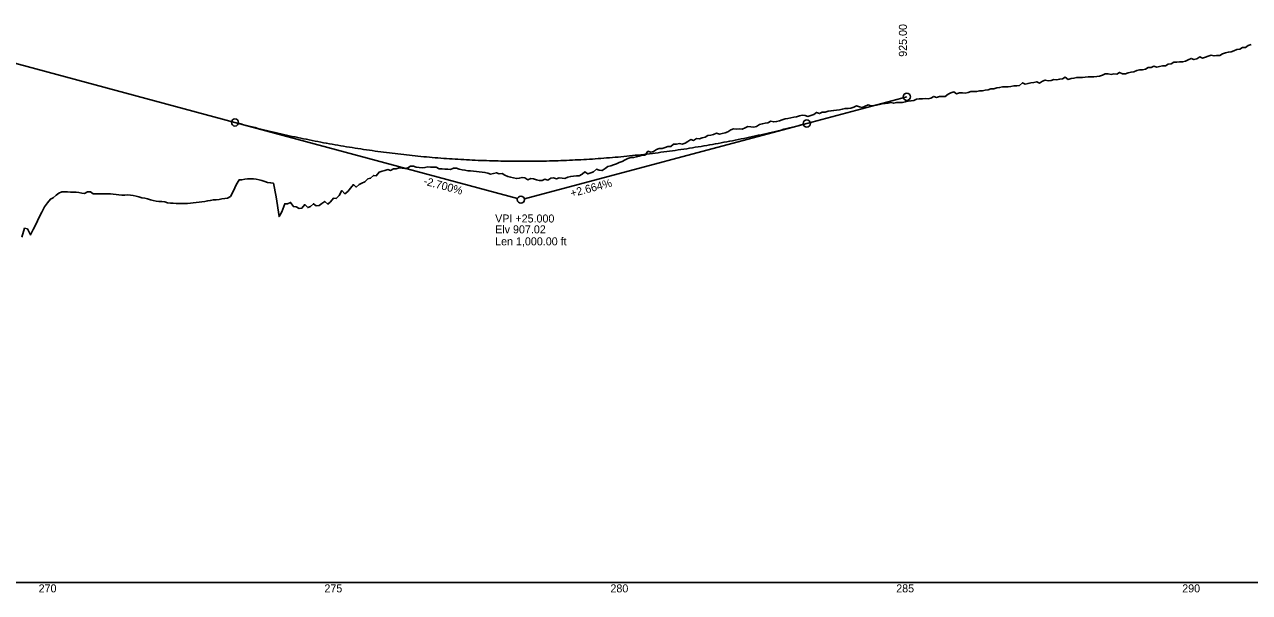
# Model space of a CAD drawing. Extents: x 5180909 to 5237144, y 3695282 to 3720102.
# Drawn here: x 5230717 to 5232860, y 3697765 to 3698758 of the extents above; entities that cross this region are included whole.
import ezdxf

# ---------------------------------------------------------------- set-up
doc = ezdxf.new("R2010")
doc.units = 0
for name, color, linetype in [('dsnEntranceGranular', 7, 'Continuous'), ('dsnShoulderGran', 7, 'Continuous'), ('dsnShoulderPaved', 7, 'Continuous'), ('dsnStgShadingPropGrdLim', 7, 'Continuous'), ('EdgeShoulder', 7, 'Continuous'), ('Entrance', 7, 'Continuous')]:
    doc.layers.add(name, color=color, linetype=linetype)

msp = doc.modelspace()

# ---------------------------------------------------------------- linework, layer by layer
at = {"layer": 'dsnEntranceGranular'}
msp.add_line((5221643.6, 3697782), (5237143.6, 3697782), dxfattribs=at)
at = {"layer": 'dsnShoulderPaved'}
for points in [[(5232642.7, 3698672.4), (5232647.7, 3698674.2), (5232652.7, 3698675.2), (5232657.7, 3698675.8), (5232662.7, 3698677.9), (5232667.7, 3698678.9), (5232672.7, 3698679), (5232677.7, 3698680.2), (5232682.7, 3698683.2), (5232687.7, 3698683.4), (5232692.7, 3698685.6), (5232697.7, 3698683.6), (5232702.7, 3698685.1), (5232707.7, 3698685.9), (5232712.7, 3698686.4), (5232717.7, 3698688.8), (5232722.7, 3698689.4), (5232727.7, 3698692.5), (5232732.7, 3698692.5), (5232737.7, 3698692.9), (5232742.7, 3698693), (5232747.7, 3698694.6), (5232752.7, 3698696.4), (5232757.7, 3698699.2), (5232762.7, 3698697.2), (5232767.7, 3698698.2), (5232772.7, 3698701.8), (5232777.7, 3698699.4), (5232782.7, 3698701.5), (5232787.7, 3698702.8), (5232792.7, 3698704.7), (5232797.7, 3698703.4), (5232802.7, 3698704.3), (5232807.7, 3698704.4), (5232812.7, 3698707.4), (5232817.7, 3698709.2), (5232822.7, 3698709.8), (5232827.7, 3698710.9), (5232832.7, 3698712.3), (5232837.7, 3698715), (5232842.7, 3698715.2), (5232847.7, 3698718.3), (5232852.7, 3698718.3), (5232857.7, 3698721.6), (5232862.7, 3698723.6)], [(5232142.7, 3698609), (5232147.7, 3698610.3), (5232152.7, 3698611.8), (5232157.7, 3698611.8), (5232162.7, 3698612.1), (5232167.7, 3698613.9), (5232172.7, 3698616), (5232177.7, 3698614.5), (5232182.7, 3698613.5), (5232187.7, 3698615.6), (5232192.7, 3698618.1), (5232197.7, 3698616.2), (5232202.7, 3698616.5), (5232207.7, 3698617.6), (5232212.7, 3698618.6), (5232217.7, 3698619.5), (5232222.7, 3698620.3), (5232227.7, 3698621.1), (5232232.7, 3698621.9), (5232237.7, 3698620.8), (5232242.7, 3698622.3), (5232247.7, 3698622.3), (5232252.7, 3698622.1), (5232257.7, 3698623), (5232262.7, 3698624.3), (5232267.7, 3698624.9), (5232272.7, 3698625.8), (5232277.7, 3698627.6), (5232282.7, 3698628.7), (5232287.7, 3698628.6), (5232292.7, 3698629.1), (5232297.7, 3698628.5), (5232302.7, 3698629.4), (5232307.7, 3698632.6), (5232312.7, 3698630.9), (5232317.7, 3698632.7), (5232322.7, 3698632.7), (5232327.7, 3698632.7), (5232332.7, 3698636.5), (5232337.7, 3698638.8), (5232342.7, 3698640.5), (5232347.7, 3698637.4), (5232352.7, 3698638.7), (5232357.7, 3698638.8), (5232362.7, 3698638.6), (5232367.7, 3698639.8), (5232372.7, 3698641.2), (5232377.7, 3698641), (5232382.7, 3698641.4), (5232387.7, 3698642.3), (5232392.7, 3698642.7), (5232397.7, 3698643.8), (5232402.7, 3698643.9), (5232407.7, 3698645.9), (5232412.7, 3698645.9), (5232417.7, 3698647.4), (5232422.7, 3698648.1), (5232427.7, 3698649.4), (5232432.7, 3698649.3), (5232437.7, 3698649.7), (5232442.7, 3698650.3), (5232447.7, 3698651.1), (5232452.7, 3698651.1), (5232457.7, 3698652), (5232462.7, 3698656.5), (5232467.7, 3698654.3), (5232472.7, 3698655.5), (5232477.7, 3698656.4), (5232482.7, 3698657.2), (5232487.7, 3698658.4), (5232492.7, 3698656), (5232497.7, 3698659.1), (5232502.7, 3698661.2), (5232507.7, 3698660.2), (5232512.7, 3698660.5), (5232517.7, 3698662.2), (5232522.7, 3698661.8), (5232527.7, 3698662.6), (5232532.7, 3698663.7), (5232537.7, 3698666.1), (5232542.7, 3698662.5), (5232547.7, 3698663.8), (5232552.7, 3698664.5), (5232557.7, 3698665.9), (5232562.7, 3698665.5), (5232567.7, 3698665.8), (5232572.7, 3698666.3), (5232577.7, 3698667), (5232582.7, 3698667), (5232587.7, 3698667), (5232592.7, 3698667.4), (5232597.7, 3698667.9), (5232602.7, 3698670), (5232607.7, 3698672.1), (5232612.7, 3698672), (5232617.7, 3698671.2), (5232622.7, 3698672), (5232627.7, 3698671.6), (5232632.7, 3698674.7), (5232637.7, 3698672), (5232642.7, 3698672.4)], [(5231642.7, 3698490.2), (5231647.7, 3698488.3), (5231652.7, 3698490.4), (5231657.7, 3698489.6), (5231662.7, 3698488.8), (5231667.7, 3698491.2), (5231672.7, 3698492.7), (5231677.7, 3698493.1), (5231682.7, 3698493.7), (5231687.7, 3698494), (5231692.7, 3698496.5), (5231697.7, 3698500.5), (5231702.7, 3698497), (5231707.7, 3698498.8), (5231712.7, 3698501), (5231717.7, 3698505.1), (5231722.7, 3698503.7), (5231727.7, 3698502.8), (5231732.7, 3698506.4), (5231737.7, 3698509.9), (5231742.7, 3698511.5), (5231747.7, 3698512.9), (5231752.7, 3698514.7), (5231757.7, 3698517.3), (5231762.7, 3698519), (5231767.7, 3698521.9), (5231772.7, 3698523.9), (5231777.7, 3698525.8), (5231782.7, 3698525.7), (5231787.7, 3698527), (5231792.7, 3698528), (5231797.7, 3698529.8), (5231802.7, 3698530.1), (5231807.7, 3698536.7), (5231812.7, 3698535.2), (5231817.7, 3698536.5), (5231822.7, 3698539.6), (5231827.7, 3698541.5), (5231832.7, 3698541.8), (5231837.7, 3698543.2), (5231842.7, 3698544.9), (5231847.7, 3698544.8), (5231852.7, 3698549.1), (5231857.7, 3698549.3), (5231862.7, 3698550.2), (5231867.7, 3698549.1), (5231872.7, 3698550.8), (5231877.7, 3698553.7), (5231882.7, 3698557), (5231887.7, 3698555.8), (5231892.7, 3698559.3), (5231897.7, 3698558.6), (5231902.7, 3698560), (5231907.7, 3698561.5), (5231912.7, 3698564), (5231917.7, 3698564.6), (5231922.7, 3698566), (5231927.7, 3698568.3), (5231932.7, 3698566.8), (5231937.7, 3698567.8), (5231942.7, 3698568.8), (5231947.7, 3698570.9), (5231952.7, 3698574.1), (5231957.7, 3698575.8), (5231962.7, 3698575.4), (5231967.7, 3698575.7), (5231972.7, 3698575.5), (5231977.7, 3698577.8), (5231982.7, 3698580), (5231987.7, 3698579.5), (5231992.7, 3698579), (5231997.7, 3698580.3), (5232002.7, 3698583.5), (5232007.7, 3698584.5), (5232012.7, 3698585.8), (5232017.7, 3698586.5), (5232022.7, 3698589.5), (5232027.7, 3698588.1), (5232032.7, 3698588.5), (5232037.7, 3698590), (5232042.7, 3698591.7), (5232047.7, 3698593.4), (5232052.7, 3698594.3), (5232057.7, 3698595.4), (5232062.7, 3698596.3), (5232067.7, 3698597.2), (5232072.7, 3698598.8), (5232077.7, 3698600.1), (5232082.7, 3698599.4), (5232087.7, 3698597.8), (5232092.7, 3698599.5), (5232097.7, 3698601.2), (5232102.7, 3698604.7), (5232107.7, 3698602.6), (5232112.7, 3698605), (5232117.7, 3698605.2), (5232122.7, 3698606.6), (5232127.7, 3698607.2), (5232132.7, 3698608.3), (5232137.7, 3698608.6), (5232142.7, 3698609)], [(5231142.7, 3698481.8), (5231147.7, 3698481.6), (5231152.7, 3698480.7), (5231157.7, 3698456.8), (5231162.7, 3698422.4), (5231167.7, 3698431), (5231172.7, 3698444.9), (5231177.7, 3698444.6), (5231182.7, 3698447.3), (5231187.7, 3698440), (5231192.7, 3698439.5), (5231197.7, 3698436.6), (5231202.7, 3698437.2), (5231207.7, 3698443.3), (5231212.7, 3698438.1), (5231217.7, 3698440.1), (5231222.7, 3698444.8), (5231227.7, 3698441.4), (5231232.7, 3698441.8), (5231237.7, 3698445.6), (5231242.7, 3698449.1), (5231247.7, 3698444.4), (5231252.7, 3698448.5), (5231257.7, 3698454.6), (5231262.7, 3698454.1), (5231267.7, 3698459.4), (5231272.7, 3698467.8), (5231277.7, 3698462.5), (5231282.7, 3698466.6), (5231287.7, 3698471.9), (5231292.7, 3698478.5), (5231297.7, 3698474.1), (5231302.7, 3698478.5), (5231307.7, 3698480.7), (5231312.7, 3698483.1), (5231317.7, 3698488.3), (5231322.7, 3698489.5), (5231327.7, 3698494.4), (5231332.7, 3698493.8), (5231337.7, 3698500.1), (5231342.7, 3698501.6), (5231347.7, 3698503), (5231352.7, 3698504.6), (5231357.7, 3698503.1), (5231362.7, 3698505.7), (5231367.7, 3698506), (5231372.7, 3698507.5), (5231377.7, 3698507.3), (5231382.7, 3698506.5), (5231387.7, 3698507.6), (5231392.7, 3698510.4), (5231397.7, 3698510.6), (5231402.7, 3698508.8), (5231407.7, 3698508.4), (5231412.7, 3698507.8), (5231417.7, 3698508.2), (5231422.7, 3698509.2), (5231427.7, 3698508.9), (5231432.7, 3698508.9), (5231437.7, 3698508.7), (5231442.7, 3698506), (5231447.7, 3698505.8), (5231452.7, 3698505.6), (5231457.7, 3698505.5), (5231462.7, 3698504.9), (5231467.7, 3698507), (5231472.7, 3698507.2), (5231477.7, 3698505.2), (5231482.7, 3698504.4), (5231487.7, 3698503.7), (5231492.7, 3698502.6), (5231497.7, 3698502.3), (5231502.7, 3698502), (5231507.7, 3698501.5), (5231512.7, 3698500.7), (5231517.7, 3698500), (5231522.7, 3698499.6), (5231527.7, 3698498.2), (5231532.7, 3698496.8), (5231537.7, 3698498.1), (5231542.7, 3698499.1), (5231547.7, 3698497.5), (5231552.7, 3698497.8), (5231557.7, 3698495.1), (5231562.7, 3698492.4), (5231567.7, 3698491.4), (5231572.7, 3698490.2), (5231577.7, 3698488.9), (5231582.7, 3698489.6), (5231587.7, 3698491.1), (5231592.7, 3698490), (5231597.7, 3698486.8), (5231602.7, 3698488.8), (5231607.7, 3698488.5), (5231612.7, 3698486.8), (5231617.7, 3698485.3), (5231622.7, 3698485.6), (5231627.7, 3698487.9), (5231632.7, 3698486.4), (5231637.7, 3698489.8), (5231642.7, 3698490.2)], [(5230712.7, 3698386.6), (5230717.7, 3698401.9), (5230722.7, 3698400.9), (5230727.7, 3698390.5), (5230732.7, 3698399.6), (5230737.7, 3698410), (5230742.7, 3698420.5), (5230747.7, 3698430.3), (5230752.7, 3698439.4), (5230757.7, 3698446.2), (5230762.7, 3698452.7), (5230767.7, 3698455.2), (5230772.7, 3698460.1), (5230777.7, 3698463.5), (5230782.7, 3698466), (5230787.7, 3698465.9), (5230792.7, 3698465.6), (5230797.7, 3698465.4), (5230802.7, 3698465.2), (5230807.7, 3698465.1), (5230812.7, 3698464.3), (5230817.7, 3698463.6), (5230822.7, 3698462.9), (5230827.7, 3698465.9), (5230832.7, 3698465.8), (5230837.7, 3698462.3), (5230842.7, 3698462.1), (5230847.7, 3698462.1), (5230852.7, 3698462.1), (5230857.7, 3698462), (5230862.7, 3698462), (5230867.7, 3698462.1), (5230872.7, 3698461.5), (5230877.7, 3698461), (5230882.7, 3698460.3), (5230887.7, 3698459.7), (5230892.7, 3698459.9), (5230897.7, 3698460.2), (5230902.7, 3698460.1), (5230907.7, 3698459.3), (5230912.7, 3698458.4), (5230917.7, 3698457), (5230922.7, 3698455.5), (5230927.7, 3698454.4), (5230932.7, 3698453.2), (5230937.7, 3698451.8), (5230942.7, 3698450.5), (5230947.7, 3698449.6), (5230952.7, 3698448.7), (5230957.7, 3698448.6), (5230962.7, 3698448.1), (5230967.7, 3698446.5), (5230972.7, 3698446.1), (5230977.7, 3698446), (5230982.7, 3698445.6), (5230987.7, 3698445.3), (5230992.7, 3698445.1), (5230997.7, 3698445.3), (5231002.7, 3698445.6), (5231007.7, 3698445.9), (5231012.7, 3698446.5), (5231017.7, 3698447.3), (5231022.7, 3698447.9), (5231027.7, 3698448.5), (5231032.7, 3698449), (5231037.7, 3698449.7), (5231042.7, 3698450.7), (5231047.7, 3698451.5), (5231052.7, 3698452), (5231057.7, 3698452.6), (5231062.7, 3698453.6), (5231067.7, 3698454.1), (5231072.7, 3698454.6), (5231077.7, 3698457.6), (5231082.7, 3698467.5), (5231087.7, 3698477.8), (5231092.7, 3698486.7), (5231097.7, 3698487), (5231102.7, 3698487.7), (5231107.7, 3698488.4), (5231112.7, 3698488.5), (5231117.7, 3698488.3), (5231122.7, 3698487.7), (5231127.7, 3698486.6), (5231132.7, 3698485.5), (5231137.7, 3698483.7), (5231142.7, 3698481.8)]]:
    msp.add_lwpolyline(points, dxfattribs=at)
at = {"layer": 'dsnStgShadingPropGrdLim'}
for p, q in [((5230685.6, 3698695.1), (5231085.6, 3698587.1)), ((5232085.6, 3698585.3), (5232260.6, 3698632))]:
    msp.add_line(p, q, dxfattribs=at)
msp.add_spline([(5231085.6, 3698587.1), (5231105.6, 3698581.8), (5231125.6, 3698576.8), (5231145.6, 3698571.9), (5231165.6, 3698567.3), (5231185.6, 3698562.8), (5231205.6, 3698558.6), (5231225.6, 3698554.6), (5231245.6, 3698550.8), (5231265.6, 3698547.2), (5231285.6, 3698543.9), (5231305.6, 3698540.7), (5231325.6, 3698537.8), (5231345.6, 3698535.1), (5231365.6, 3698532.6), (5231385.6, 3698530.3), (5231405.6, 3698528.2), (5231425.6, 3698526.3), (5231445.6, 3698524.7), (5231465.6, 3698523.3), (5231485.6, 3698522.1), (5231505.6, 3698521), (5231525.6, 3698520.3), (5231545.6, 3698519.7), (5231565.6, 3698519.3), (5231585.6, 3698519.2), (5231605.6, 3698519.3), (5231625.6, 3698519.5), (5231645.6, 3698520), (5231665.6, 3698520.8), (5231685.6, 3698521.7), (5231705.6, 3698522.8), (5231725.6, 3698524.2), (5231745.6, 3698525.8), (5231765.6, 3698527.6), (5231785.6, 3698529.6), (5231805.6, 3698531.8), (5231825.6, 3698534.2), (5231845.6, 3698536.9), (5231865.6, 3698539.7), (5231885.6, 3698542.8), (5231905.6, 3698546.1), (5231925.6, 3698549.6), (5231945.6, 3698553.3), (5231965.6, 3698557.2), (5231985.6, 3698561.4), (5232005.6, 3698565.7), (5232025.6, 3698570.3), (5232045.6, 3698575.1), (5232065.6, 3698580.1), (5232085.6, 3698585.3)], degree=3, dxfattribs=at)
at = {"layer": 'Entrance'}
for p, q in [((5231085.6, 3698587.1), (5231579.6, 3698453.8)), ((5232085.6, 3698585.3), (5231591.7, 3698453.7))]:
    msp.add_line(p, q, dxfattribs=at)
for centre in [(5232260.6, 3698632), (5231085.6, 3698587.1), (5232085.6, 3698585.3), (5231585.6, 3698452.1)]:
    msp.add_circle(centre, 6.25, dxfattribs=at)

# ---------------------------------------------------------------- texts
at = {"layer": 'dsnShoulderGran'}
for s, p in [('270', (5230742.2, 3697765)), ('275', (5231242, 3697765)), ('280', (5231742.2, 3697765)), ('285', (5232242, 3697765)), ('290', (5232742.2, 3697765))]:
    msp.add_text(s, height=14, dxfattribs=at).set_placement(p)
at = {"layer": 'EdgeShoulder'}
for s, rotation, p in [('925.00', 90, (5232260.6, 3698702)), ('-2.700%', 344.8904, (5231414.3, 3698478.7)), ('+2.664%', 14.9178, (5231674.2, 3698456.1))]:
    msp.add_text(s, height=14, rotation=rotation, dxfattribs=at).set_placement(p)
for s, p in [('VPI +25.000', (5231540.6, 3698412.1)), ('Elv 907.02', (5231540.6, 3698393.1)), ('Len 1,000.00 ft', (5231540.6, 3698372.1))]:
    msp.add_text(s, height=14, dxfattribs=at).set_placement(p)

doc.saveas('drawing.dxf')
